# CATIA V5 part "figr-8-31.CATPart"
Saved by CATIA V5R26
Part number: Part1
Bounding box of the stored display mesh (mm): x -50 to 50, y -75 to 125, z 0 to 40
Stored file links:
  D:\_Deepak\CATIA\CATIA V5-6R2016_Deepak\Resources\Part files\Partfiles\c08_catia_v5_6r2016_prt\figr-8-31.CATPart
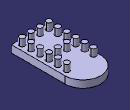
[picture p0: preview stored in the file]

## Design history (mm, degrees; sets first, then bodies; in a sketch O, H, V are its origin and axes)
Body1 (main body)
  Sketch1 on xy-plane, origin (0, 0, 0), H (1, 0, 0), V (0, 1, 0)
    line L1 (50, 75) -> (50, -75)
    line L2 (50, -75) -> (-50, -75)
    line L3 (-50, -75) -> (-50, 75)
    arc A1 centre (0, 75) radius 50 from (-50, 75) to (50, 75) cw
    point P5 (0, 75)
    axis line L4 (50, -75) -> (-50, 75)
    length L2 = 100
    distance P5 L2 = 150
    horizontal: L2 H
    vertical: L1 V, L3 V
    tangency: A1 L3, A1 L1
    midpoint: O L4
  Pad1: profile Sketch1, direction (0, 0, 1), length 20
  Sketch2 on face of Pad1, origin (0, 0, 20), H (1, 0, 0), V (0, 1, 0)
    circle A1 centre (35, -60) radius 7.5
    point P1 (35, -60)
    reference projected line E1 (-50, -75) -> (50, -75) from edge [face of Pad1 | face of Pad1]
    reference projected line E2 (50, -75) -> (50, 75) from edge [face of Pad1 | face of Pad1]
    distance P1 E1 = 15
    distance P1 E2 = 15
    radius A1 = 7.5
  Pad2: profile Sketch2, direction (0, 0, 1), length 20
  RectPattern1: of Pad2, direction 1 instances 4, spacing 25, along edge [face of Pad1 | face of Pad1] reversed, direction 2 instances 6, spacing 25, along edge [face of Pad1 | face of Pad1]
